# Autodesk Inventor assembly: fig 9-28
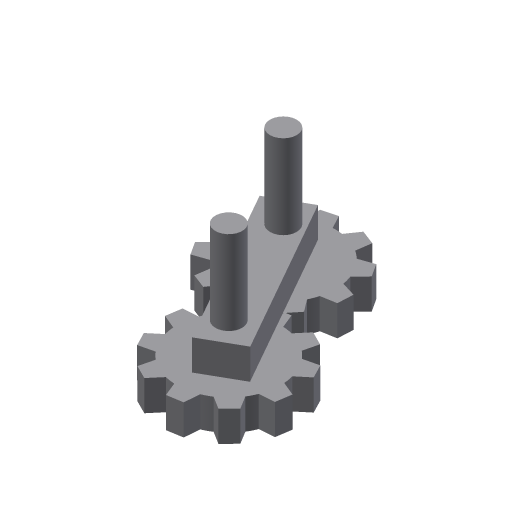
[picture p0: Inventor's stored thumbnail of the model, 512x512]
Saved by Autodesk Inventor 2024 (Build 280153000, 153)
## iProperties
Created: 2017-05
Part Number: fig 9-28
Document SubType Name: Assembly
Designer: CADCIM 00
Author: CADCIM 00
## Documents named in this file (3)
- D:\PROJECTS\Project 2023\RESOURCES INVENTOR 2024\RESOURCES INVENTOR 2024\Inventor_2023_Part\Inventor_2024_Part\c09_Inv_2024_prt\fig 9-28.iam
- D:\PROJECTS\Project 2023\RESOURCES INVENTOR 2024\RESOURCES INVENTOR 2024\Inventor_2023_Part\Inventor_2024_Part\c09_Inv_2024_prt\1.ipt
- D:\PROJECTS\Project 2023\RESOURCES INVENTOR 2024\RESOURCES INVENTOR 2024\Inventor_2023_Part\Inventor_2024_Part\c09_Inv_2024_prt\2.ipt
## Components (3 placed, 2 different names)
1. 1:1 — Flush:1, Rotation:1, Insert:2
2. 1:2 — Flush:1, Rotation:1, Insert:1
3. 2:1 — Insert:1, Insert:2
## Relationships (4: Insert 2, Flush 1, RelateRotation 1)
- Flush:1: 1:1 ↔ 1:2
- Rotation:1 [RelateRotation]: 1:1 ↔ 1:2
- Insert:1: 1:2 ↔ 2:1
- Insert:2: 1:1 ↔ 2:1
